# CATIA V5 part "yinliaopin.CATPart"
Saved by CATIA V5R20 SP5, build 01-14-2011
Part number: Part1
Material "DS Light Blue": density 7860 kg/m3, Young's modulus 2e+11 Pa, Poisson ratio 0.266
Material "Wallpaper Strip 2": density 2120 kg/m3, Young's modulus 2.56e+10 Pa, Poisson ratio 0.22
Material "Fire Red": density 7860 kg/m3, Young's modulus 2e+11 Pa, Poisson ratio 0.266
Bounding box of the stored display mesh (mm): x -25 to 25, y -26 to 25, z 0 to 110
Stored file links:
  E:\3.8\yinliaopin.CATPart
  C:\Program Files\Dassault Systemes\B20\intel_a\startup\materials\Catalog.CATMaterial
  C:\Program Files\Dassault Systemes\B20\intel_a\startup\materials\blue_env_512x512.jpg
  C:\Program Files\Dassault Systemes\B20\intel_a\startup\materials\chessboard.jpg
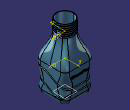
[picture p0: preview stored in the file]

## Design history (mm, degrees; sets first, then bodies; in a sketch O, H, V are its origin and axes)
Set1
  Sketch1 on face of Pad1 from Sketch3.L1, origin (25, 0, 0), H (0, 1, 0), V (0, 0, 1)
    spline S1 through (-40, 10) (-10, 20) (10, 10) (30, 20)
  Extrude1: Element1 Sketch1, Lim1 66, Lim2 66
  MultiSel1: CommonCtxFeats ({extract ExtractElem face of Fillet1}; {extract ExtractElem face of Pad1 from Sketch3.L1}; {extract ExtractElem face of Fillet1}; {extract ExtractElem face of Pad1 from Sketch3.L4}; {extract ExtractElem face of Fillet1}; {extract ExtractElem face of Pad1 from Sketch3.L3}; {extract ExtractElem face of Fillet1}; {extract ExtractElem face of Pad1 from Sketch3.L2})
  Sketch2 on face of Pad1 from Sketch3.L3, origin (-25, 0, 0), H (0, -1, 0), V (0, 0, 1)
    spline S1 through (-40, 20) (-10, 30) (10, 40) (30, 40)
  Extrude2: Element1 Sketch2, Lim1 66, Lim2 66
  MultiSel2: CommonCtxFeats ({extract ExtractElem face of Fillet1}; {extract ExtractElem face of Pad1 from Sketch3.L2}; {extract ExtractElem face of Fillet1}; {extract ExtractElem face of Pad1 from Sketch3.L1}; {extract ExtractElem face of Fillet1}; {extract ExtractElem face of Pad1 from Sketch3.L4}; {extract ExtractElem face of Fillet1}; {extract ExtractElem face of Pad1 from Sketch3.L3})
  Join1: Elements ({intersect ToIntersect1 {extract ExtractElem face of Fillet1}, ToIntersect2 Extrude2}; {intersect ToIntersect1 {extract ExtractElem face of Pad1 from Sketch3.L2}, ToIntersect2 Extrude2}; {intersect ToIntersect1 {extract ExtractElem face of Fillet1}, ToIntersect2 Extrude2}; {intersect ToIntersect1 {extract ExtractElem face of Pad1 from Sketch3.L1}, ToIntersect2 Extrude2}; {intersect ToIntersect1 {extract ExtractElem face of Fillet1}, ToIntersect2 Extrude2}; {intersect ToIntersect1 {extract ExtractElem face of Pad1 from Sketch3.L4}, ToIntersect2 Extrude2}; {intersect ToIntersect1 {extract ExtractElem face of Fillet1}, ToIntersect2 Extrude2}; {intersect ToIntersect1 {extract ExtractElem face of Pad1 from Sketch3.L3}, ToIntersect2 Extrude2})
  Join2: Elements ({intersect ToIntersect1 {extract ExtractElem face of Fillet1}, ToIntersect2 Extrude1}; {intersect ToIntersect1 {extract ExtractElem face of Pad1 from Sketch3.L1}, ToIntersect2 Extrude1}; {intersect ToIntersect1 {extract ExtractElem face of Fillet1}, ToIntersect2 Extrude1}; {intersect ToIntersect1 {extract ExtractElem face of Pad1 from Sketch3.L4}, ToIntersect2 Extrude1}; {intersect ToIntersect1 {extract ExtractElem face of Fillet1}, ToIntersect2 Extrude1}; {intersect ToIntersect1 {extract ExtractElem face of Pad1 from Sketch3.L3}, ToIntersect2 Extrude1}; {intersect ToIntersect1 {extract ExtractElem face of Fillet1}, ToIntersect2 Extrude1}; {intersect ToIntersect1 {extract ExtractElem face of Pad1 from Sketch3.L2}, ToIntersect2 Extrude1})
  Plane1: type Normal, Curve Join1, RefPoint vertex [face of MultiSel2 | face of MultiSel2]
  Circle1: type CtrRad, Start 0, End 180, Center vertex [face of MultiSel2 | face of MultiSel2], Support Plane1, Radius 1, FirstDirection (1, 0, 0)
  Plane2: type Normal, Curve Join2, RefPoint vertex [face of MultiSel1 | face of MultiSel1]
  Circle2: type CtrRad, Start 0, End 180, Center vertex [face of MultiSel1 | face of MultiSel1], Support Plane2, Radius 1, FirstDirection (1, 0, 0)
Body1 (main body), material "DS Light Blue"
  Set2
    Sketch3 on xy-plane, origin (0, 0, 0), H (1, 0, 0), V (0, 1, 0)
      line L1 (25, 25) -> (25, -25)
      line L2 (25, -25) -> (-25, -25)
      line L3 (-25, -25) -> (-25, 25)
      line L4 (-25, 25) -> (25, 25)
      distance L2 L4 = 50
      distance L1 L3 = 50
      vertical: L1 V, L3 V
      horizontal: L2 H, L4 H
      equidistance: L1 L3 O, L2 L4 O
  Pad1: profile Sketch3, direction (0, 0, 1), length 50
  Fillet1: on edge [face of Pad1 from Sketch3.L2 | face of Pad1 from Sketch3.L3]; edge [face of Pad1 from Sketch3.L4 | face of Pad1 from Sketch3.L1]; edge [face of Pad1 from Sketch3.L3 | face of Pad1 from Sketch3.L4]; edge [face of Pad1 from Sketch3.L1 | face of Pad1 from Sketch3.L2]
  Fillet2: on edge [start face of Pad1 | face of Pad1 from Sketch3.L4]
  Plane3: type Offset, RefPlane end face of Pad1, Offset 40, reversed
  Sketch4 on Plane3, origin (0, 0, 90), H (1, 0, 0), V (0, -1, 0)
    circle A1 centre (0, 0) radius 15
    radius A1 = 15
  Pad2: profile Sketch4, direction (0, 0, -1), length -20
  Sketch5 on end face of Pad1, origin (0, 0, 50), H (1, 0, 0), V (0, 1, 0)
    point P1 (25, 0)
    distance V P1 = 25
    coincidence: P1 H
  Sketch6 on start face of Pad2, origin (0, 0, 90), H (1, 0, 0), V (0, -1, 0)
    point P1 (15, 0)
    distance P1 V = 15
    coincidence: P1 H
  Loft1: solid, Sections ({boundary Boundary {extract ExtractElem end face of Pad1}}; {boundary Boundary {extract ExtractElem start face of Pad2}}), StartFace end face of Pad1, EndFace start face of Pad2
  Slot1: profile Circle1, centre curve Join1
  Slot2: profile Circle2, centre curve Join2
  Shell1: ExtOffset 0, Face end face of Pad2, IntOffset 1
  Point1: (0, 0, 2), relative to Sketch6
  Helix1: Direction Z axis, RefPoint Point1, Pitch 3, Height 16, TaperAngle 0
  Point2: type OnCurve, Support Helix1, Length 5
  Line1: type PtDir, RefPoint Point1, Direction (1, 0, 0), Start 0, End -10
  Point3: type OnCurve, Support Line1, Length 5
  Connect1: Curve1 Line1, Point1 vertex of Line1, Tension1 1, Curve2 Helix1, Point2 Point2, Tension2 1
  Plane4: type Normal, Curve Connect1, RefPoint vertex of Connect1
  Circle3: type CtrRad, Start 0, End 180, Radius 0.5, Center vertex of Connect1, Support Plane4, FirstDirection (0, 1, 0)
  Rib1: profile Circle3, centre curve Connect1
  Body2
    Plane5: type Offset, RefPlane xy-plane, Offset 2
    Sketch7 on Plane5, origin (0, 0, 2), H (1, 0, 0), V (0, 1, 0)
      circle A1 centre (0, 0) radius 14
    Pad3: profile Sketch7, direction (0, 0, 1), length 120
  Remove1: tool Body2
Body3
Body4, material "Wallpaper Strip 2"
  Sketch8 on face of Pad1 from Sketch3.L2, origin (0, -25, 0), H (1, 0, 0), V (0, 0, 1)
    polyline C1
    polyline C2
    polyline C3
    polyline C4
    polyline C5
    polyline C6
    polyline C7
    polyline C8
    polyline C9
    polyline C10
    polyline C11
  Pad4: profile Sketch8, direction (0, -1, 0), length 1
Body5, material "Fire Red"
  Sketch9 on face of Pad1 from Sketch3.L4, origin (0, 25, 0), H (-1, 0, 0), V (0, 0, 1)
    polyline C1
    polyline C2
    polyline C3
    polyline C4
    polyline C5
    polyline C6
    polyline C7
    polyline C8
    polyline C9
    polyline C10
    polyline C11
    polyline C12
  Pocket1: profile Sketch9, direction (0, -1, 0), length 2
